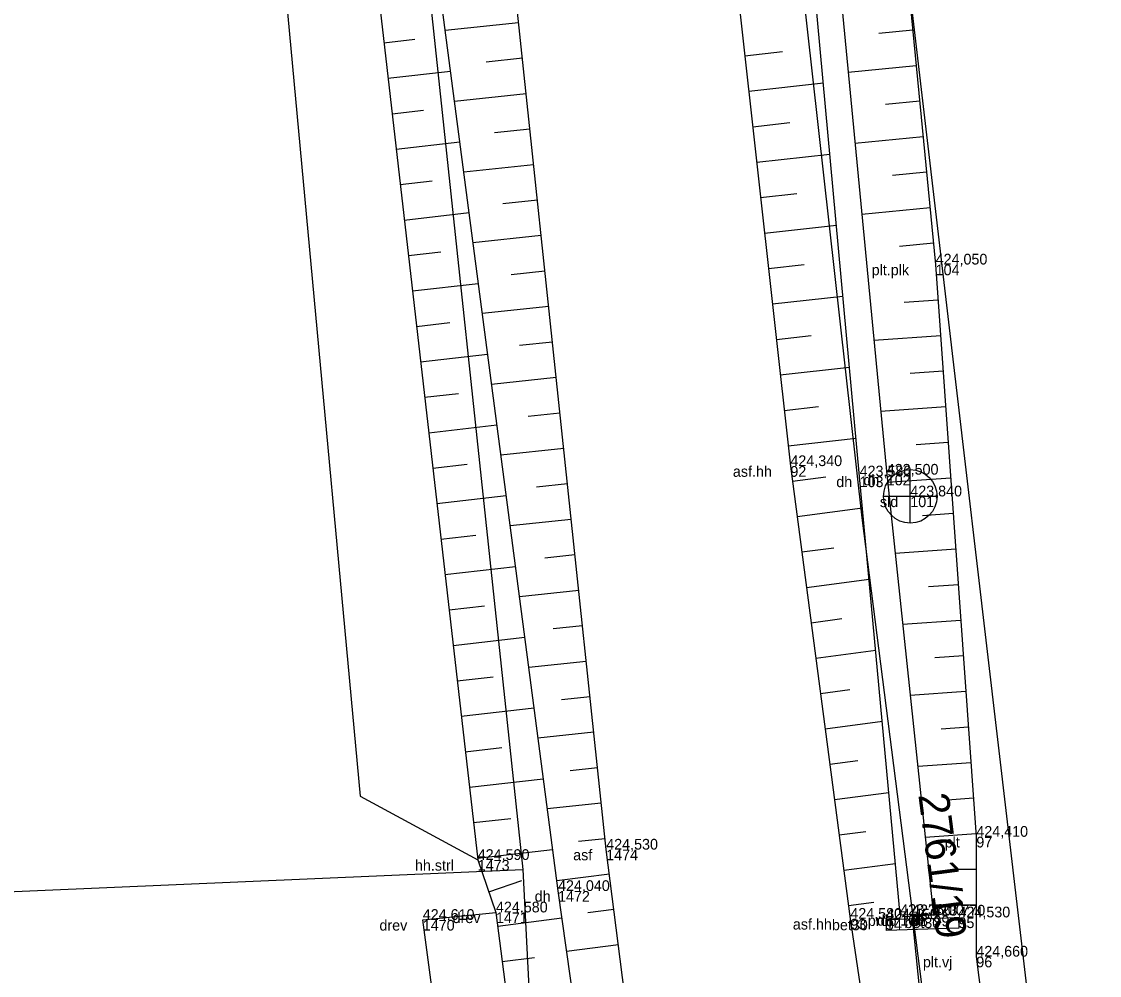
# Model space of a CAD drawing. Extents: x -747792 to -745414, y -1093712 to -1091463.
# Drawn here: x -746652 to -746621.8, y -1092774.61 to -1092747.87 of the extents above; entities that cross this region are included whole.
import ezdxf

# ---------------------------------------------------------------- set-up
doc = ezdxf.new("R2010")
doc.units = 0
for name, color, linetype in [('Hladina', 7, 'Continuous'), ('Koleje_dopravní prvky', 7, 'Continuous'), ('Nezařazené objekty', 7, 'Continuous'), ('Nivelační značky_hrany', 7, 'Continuous'), ('Pracovní_bod JDTM STC_VC - výška', 7, 'Continuous'), ('Pracovní_bod PPBP', 7, 'Continuous'), ('Pracovní_bod PPBP - výška', 7, 'Continuous'), ('Pracovní_bod ZPBP', 7, 'Continuous'), ('Rozhraní ploch', 7, 'Continuous'), ('Stromy_porost', 7, 'Continuous'), ('Výškopis', 7, 'Continuous'), ('Čísla popisná_parcelní', 7, 'Continuous')]:
    doc.layers.add(name, color=color, linetype=linetype)

msp = doc.modelspace()

# ---------------------------------------------------------------- linework, layer by layer
at = {"layer": 'Hladina'}
for p, q in [((-746626.39, -1092754.68), (-746626.39, -1092754.68)), ((-746630.46, -1092760.33), (-746630.46, -1092760.33)), ((-746628.52, -1092760.62), (-746628.52, -1092760.62)), ((-746627.76, -1092760.57), (-746627.76, -1092760.57)), ((-746627.1, -1092761.18), (-746627.1, -1092761.18)), ((-746625.25, -1092770.72), (-746625.25, -1092770.72)), ((-746635.62, -1092771.08), (-746635.62, -1092771.08)), ((-746639.22, -1092771.37), (-746639.22, -1092771.37)), ((-746636.97, -1092772.24), (-746636.97, -1092772.24)), ((-746640.76, -1092773.05), (-746640.76, -1092773.05)), ((-746638.71, -1092772.84), (-746638.71, -1092772.84)), ((-746628.78, -1092773.02), (-746628.78, -1092773.02)), ((-746627.78, -1092773.04), (-746627.78, -1092773.04)), ((-746627.38, -1092772.91), (-746627.38, -1092772.91)), ((-746627.05, -1092772.92), (-746627.05, -1092772.92)), ((-746626.45, -1092772.93), (-746626.45, -1092772.93)), ((-746625.75, -1092772.98), (-746625.75, -1092772.98)), ((-746625.25, -1092774.08), (-746625.25, -1092774.08))]:
    msp.add_line(p, q, dxfattribs=at)
at = {"layer": 'Nezařazené objekty'}
for points in [[(-746630.14, -1092715.26), (-746628.51, -1092733.17), (-746628.35, -1092734.6), (-746626.39, -1092754.68)], [(-746626.39, -1092754.68), (-746625.25, -1092770.72), (-746625.25, -1092774.08)]]:
    msp.add_lwpolyline(points, dxfattribs=at)
at = {"layer": 'Nivelační značky_hrany'}
for points in [[(-746638.62, -1092670.38), (-746639.61, -1092674.4), (-746639.44, -1092678.91), (-746638.64, -1092688.08), (-746636.95, -1092702.22), (-746635.07, -1092718.24), (-746633.98, -1092729.35), (-746632.34, -1092743.37), (-746630.46, -1092760.33), (-746628.78, -1092773.02)], [(-746631.6, -1092801.51), (-746633.92, -1092784.4), (-746635.62, -1092771.08), (-746639.35, -1092735.86), (-746639.676, -1092733.06)], [(-746637.46, -1092782.53), (-746639.44, -1092782.93), (-746640.76, -1092773.05), (-746638.71, -1092772.84)], [(-746628.78, -1092773.02), (-746627.15, -1092784.02)], [(-746627.78, -1092773.04), (-746625.75, -1092772.98), (-746625.74, -1092773.28), (-746627.77, -1092773.35), (-746627.78, -1092773.04)]]:
    msp.add_lwpolyline(points, dxfattribs=at)
at = {"layer": 'Pracovní_bod JDTM STC_VC - výška'}
msp.add_lwpolyline([(-746643.3, -1092735.81), (-746645.71, -1092735.11), (-746642.51, -1092769.58), (-746639.22, -1092771.37)], dxfattribs=at)
at = {"layer": 'Pracovní_bod PPBP'}
for points in [[(-746627.38, -1092772.91), (-746628.52, -1092760.62), (-746630.29, -1092741.41), (-746632.24, -1092721.4), (-746632.95, -1092711.71), (-746633.31, -1092703.22), (-746634.38, -1092695.54), (-746635.8, -1092684.01), (-746637.93, -1092670.61)], [(-746637.24, -1092670.41), (-746635.08, -1092683.82), (-746633.69, -1092695.33), (-746632.62, -1092703.25), (-746632.27, -1092711.5), (-746631.46, -1092721.1), (-746629.61, -1092741.3), (-746627.76, -1092760.57), (-746626.45, -1092772.93)], [(-746633.23, -1092801.81), (-746633.34, -1092799.18), (-746635.14, -1092785.2), (-746636.97, -1092772.24), (-746642.05, -1092733.51)], [(-746643.6, -1092733.57), (-746643.3, -1092735.81), (-746639.22, -1092771.37), (-746638.71, -1092772.84), (-746637.46, -1092782.53), (-746636.71, -1092786.88), (-746634.79, -1092797.88), (-746635.62, -1092802.2)], [(-746638.074, -1092747.904), (-746640.133, -1092748.122)], [(-746627.031, -1092748.113), (-746627.985, -1092748.206)], [(-746641.848, -1092748.467), (-746640.981, -1092748.368)], [(-746637.969, -1092748.899), (-746638.986, -1092749.006)], [(-746631.735, -1092748.829), (-746630.681, -1092748.712)], [(-746626.934, -1092749.108), (-746628.843, -1092749.294)], [(-746641.734, -1092749.46), (-746639.984, -1092749.26)], [(-746631.625, -1092749.823), (-746629.536, -1092749.591)], [(-746637.864, -1092749.893), (-746639.873, -1092750.106)], [(-746626.837, -1092750.103), (-746627.792, -1092750.197)], [(-746641.62, -1092750.454), (-746640.737, -1092750.353)], [(-746631.515, -1092750.817), (-746630.479, -1092750.702)], [(-746637.758, -1092750.888), (-746638.751, -1092750.993)], [(-746641.506, -1092751.447), (-746639.724, -1092751.243)], [(-746626.74, -1092751.099), (-746628.651, -1092751.285)], [(-746631.404, -1092751.811), (-746629.353, -1092751.583)], [(-746637.653, -1092751.882), (-746639.613, -1092752.09)], [(-746626.642, -1092752.094), (-746627.599, -1092752.187)], [(-746641.392, -1092752.441), (-746640.493, -1092752.338)], [(-746631.294, -1092752.805), (-746630.278, -1092752.692)], [(-746637.548, -1092752.876), (-746638.515, -1092752.979)], [(-746626.545, -1092753.089), (-746628.46, -1092753.276)], [(-746641.278, -1092753.434), (-746639.464, -1092753.226)], [(-746631.184, -1092753.798), (-746629.169, -1092753.575)], [(-746637.443, -1092753.871), (-746639.353, -1092754.073)], [(-746641.164, -1092754.428), (-746640.249, -1092754.323)], [(-746626.448, -1092754.084), (-746627.406, -1092754.178)], [(-746637.337, -1092754.865), (-746638.28, -1092754.965)], [(-746631.074, -1092754.792), (-746630.076, -1092754.682)], [(-746641.05, -1092755.421), (-746639.204, -1092755.21)], [(-746637.232, -1092755.86), (-746639.093, -1092756.057)], [(-746630.964, -1092755.786), (-746628.986, -1092755.567)], [(-746626.319, -1092755.677), (-746627.268, -1092755.745)], [(-746640.936, -1092756.415), (-746640.005, -1092756.308)], [(-746630.853, -1092756.78), (-746629.874, -1092756.672)], [(-746626.248, -1092756.675), (-746628.121, -1092756.808)], [(-746637.127, -1092756.854), (-746638.045, -1092756.951)], [(-746640.822, -1092757.408), (-746638.944, -1092757.193)], [(-746630.743, -1092757.774), (-746628.802, -1092757.559)], [(-746626.177, -1092757.672), (-746627.101, -1092757.738)], [(-746637.021, -1092757.849), (-746638.832, -1092758.04)], [(-746640.708, -1092758.402), (-746639.761, -1092758.293)], [(-746636.916, -1092758.843), (-746637.809, -1092758.938)], [(-746630.633, -1092758.768), (-746629.672, -1092758.661)], [(-746626.106, -1092758.67), (-746627.93, -1092758.8)], [(-746640.594, -1092759.395), (-746638.684, -1092759.176)], [(-746630.523, -1092759.762), (-746628.619, -1092759.551)], [(-746626.036, -1092759.667), (-746626.935, -1092759.731)], [(-746636.811, -1092759.837), (-746638.572, -1092760.024)], [(-746640.48, -1092760.389), (-746639.517, -1092760.278)], [(-746630.404, -1092760.755), (-746629.467, -1092760.631)], [(-746625.965, -1092760.665), (-746627.737, -1092760.791)], [(-746636.705, -1092760.832), (-746637.574, -1092760.924)], [(-746640.366, -1092761.382), (-746638.423, -1092761.159)], [(-746630.273, -1092761.746), (-746628.438, -1092761.503)], [(-746636.6, -1092761.826), (-746638.312, -1092762.008)], [(-746625.894, -1092761.662), (-746626.762, -1092761.724)], [(-746640.252, -1092762.376), (-746639.273, -1092762.263)], [(-746630.141, -1092762.737), (-746629.243, -1092762.619)], [(-746625.823, -1092762.66), (-746627.526, -1092762.781)], [(-746636.495, -1092762.821), (-746637.338, -1092762.91)], [(-746640.138, -1092763.369), (-746638.163, -1092763.143)], [(-746630.01, -1092763.729), (-746628.253, -1092763.496)], [(-746625.752, -1092763.657), (-746626.586, -1092763.717)], [(-746636.389, -1092763.815), (-746638.052, -1092763.991)], [(-746640.024, -1092764.363), (-746639.029, -1092764.248)], [(-746629.879, -1092764.72), (-746629.02, -1092764.606)], [(-746636.284, -1092764.81), (-746637.103, -1092764.896)], [(-746625.681, -1092764.655), (-746627.315, -1092764.771)], [(-746639.91, -1092765.356), (-746637.903, -1092765.126)], [(-746629.748, -1092765.712), (-746628.068, -1092765.489)], [(-746636.179, -1092765.804), (-746637.792, -1092765.975)], [(-746625.61, -1092765.652), (-746626.41, -1092765.709)], [(-746639.796, -1092766.35), (-746638.785, -1092766.234)], [(-746629.616, -1092766.703), (-746628.796, -1092766.594)], [(-746625.539, -1092766.65), (-746627.104, -1092766.761)], [(-746636.073, -1092766.799), (-746636.868, -1092766.883)], [(-746639.682, -1092767.343), (-746637.643, -1092767.109)], [(-746629.485, -1092767.694), (-746627.883, -1092767.482)], [(-746635.968, -1092767.793), (-746637.532, -1092767.959)], [(-746625.468, -1092767.647), (-746626.233, -1092767.702)], [(-746639.568, -1092768.337), (-746638.54, -1092768.219)], [(-746635.863, -1092768.787), (-746636.632, -1092768.869)], [(-746629.354, -1092768.686), (-746628.572, -1092768.582)], [(-746625.397, -1092768.645), (-746626.893, -1092768.751)], [(-746639.454, -1092769.33), (-746637.383, -1092769.092)], [(-746629.223, -1092769.677), (-746627.699, -1092769.475)], [(-746625.327, -1092769.642), (-746626.057, -1092769.694)], [(-746635.757, -1092769.782), (-746637.271, -1092769.942)], [(-746639.34, -1092770.324), (-746638.296, -1092770.204)], [(-746629.091, -1092770.668), (-746628.349, -1092770.57)], [(-746625.256, -1092770.64), (-746626.682, -1092770.741)], [(-746635.652, -1092770.776), (-746636.397, -1092770.855)], [(-746639.226, -1092771.317), (-746637.123, -1092771.076)], [(-746628.96, -1092771.66), (-746627.514, -1092771.468)], [(-746635.532, -1092771.769), (-746637.007, -1092771.957)], [(-746625.25, -1092771.64), (-746625.918, -1092771.64)], [(-746638.91, -1092772.264), (-746637.981, -1092771.942)], [(-746635.405, -1092772.761), (-746636.138, -1092772.854)], [(-746628.829, -1092772.651), (-746628.125, -1092772.558)], [(-746625.25, -1092772.64), (-746626.481, -1092772.64)], [(-746638.66, -1092773.228), (-746636.863, -1092772.996)], [(-746626.45, -1092772.93), (-746627.38, -1092772.91)], [(-746635.279, -1092773.753), (-746636.73, -1092773.938)], [(-746638.532, -1092774.219), (-746637.628, -1092774.103)]]:
    msp.add_lwpolyline(points, dxfattribs=at)
at = {"layer": 'Pracovní_bod PPBP - výška'}
msp.add_lwpolyline([(-746625.25, -1092774.08), (-746624.2, -1092782.38)], dxfattribs=at)
at = {"layer": 'Pracovní_bod ZPBP'}
msp.add_lwpolyline([(-746625.93, -1092783.94), (-746627.05, -1092772.92)], dxfattribs=at)
at = {"layer": 'Stromy_porost'}
for points in [[(-746635.99, -1092694.45), (-746628.46, -1092761.78)], [(-746641.14, -1092741.73), (-746637.96, -1092771.64)], [(-746627.24, -1092745.94), (-746621.8, -1092792.34)], [(-746628.46, -1092761.78), (-746624.49, -1092792.84)], [(-746680.49, -1092773.48), (-746637.96, -1092771.64)], [(-746637.96, -1092771.64), (-746636.26, -1092805.07)]]:
    msp.add_lwpolyline(points, dxfattribs=at)
at = {"layer": 'Čísla popisná_parcelní'}
for p, q in [((-746627.101, -1092761.928), (-746627.1, -1092760.433)), ((-746626.348, -1092761.186), (-746627.848, -1092761.181))]:
    msp.add_line(p, q, dxfattribs=at)
msp.add_circle((-746627.1, -1092761.18), 0.75, dxfattribs=at)

# ---------------------------------------------------------------- texts
at = {"layer": 'Koleje_dopravní prvky'}
msp.add_text('2761/19', height=0.85, rotation=277.3689, dxfattribs=at).set_placement((-746626.876, -1092769.543))
at = {"layer": 'Rozhraní ploch'}
for s, p in [(' plt.plk', (-746628.294, -1092754.98)), ('104', (-746626.39, -1092754.98)), (' asf.hh', (-746632.182, -1092760.63)), ('92', (-746630.46, -1092760.63)), (' dh', (-746629.285, -1092760.92)), ('103', (-746628.52, -1092760.92)), (' dh', (-746628.525, -1092760.87)), ('102', (-746627.76, -1092760.87)), (' sld', (-746628.061, -1092761.48)), ('101', (-746627.1, -1092761.48)), (' plt', (-746626.249, -1092771.02)), ('97', (-746625.25, -1092771.02)), (' asf', (-746636.657, -1092771.38)), ('1474', (-746635.62, -1092771.38)), (' hh.strl', (-746641.091, -1092771.67)), ('1473', (-746639.22, -1092771.67)), (' dh', (-746637.735, -1092772.54)), ('1472', (-746636.97, -1092772.54)), (' drev', (-746642.085, -1092773.35)), ('1470', (-746640.76, -1092773.35)), (' drev', (-746640.035, -1092773.14)), ('1471', (-746638.71, -1092773.14)), (' asf.hh', (-746630.502, -1092773.32)), (' bet30', (-746629.407, -1092773.34)), ('93', (-746628.78, -1092773.32)), (' prop', (-746628.401, -1092773.22)), (' dh', (-746628.145, -1092773.21)), ('94', (-746627.78, -1092773.34)), ('100', (-746627.38, -1092773.21)), (' bet30', (-746627.377, -1092773.28)), (' dh', (-746627.215, -1092773.23)), ('98', (-746627.05, -1092773.22)), ('99', (-746626.45, -1092773.23)), ('95', (-746625.75, -1092773.28)), (' plt.vj', (-746626.858, -1092774.38)), ('96', (-746625.25, -1092774.38))]:
    msp.add_text(s, height=0.3, dxfattribs=at).set_placement(p)
at = {"layer": 'Výškopis'}
for s, p in [('424,050', (-746626.39, -1092754.68)), ('424,340', (-746630.46, -1092760.33)), ('423,580', (-746628.52, -1092760.62)), ('423,500', (-746627.76, -1092760.57)), ('423,840', (-746627.1, -1092761.18)), ('424,410', (-746625.25, -1092770.72)), ('424,530', (-746635.62, -1092771.08)), ('424,590', (-746639.22, -1092771.37)), ('424,040', (-746636.97, -1092772.24)), ('424,610', (-746640.76, -1092773.05)), ('424,580', (-746638.71, -1092772.84)), ('424,580', (-746628.78, -1092773.02)), ('424,450', (-746627.78, -1092773.04)), ('423,760', (-746627.38, -1092772.91)), ('423,700', (-746627.05, -1092772.92)), ('423,770', (-746626.45, -1092772.93)), ('424,530', (-746625.75, -1092772.98)), ('424,660', (-746625.25, -1092774.08))]:
    msp.add_text(s, height=0.3, dxfattribs=at).set_placement(p)

doc.saveas('drawing.dxf')
